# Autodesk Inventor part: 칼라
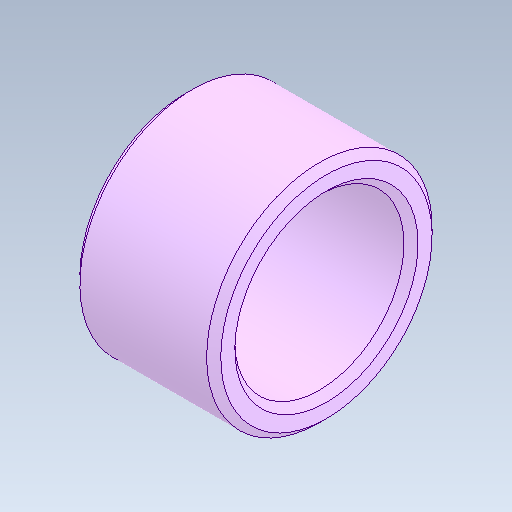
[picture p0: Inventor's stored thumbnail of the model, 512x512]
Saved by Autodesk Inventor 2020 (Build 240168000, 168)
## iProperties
Created: 2024-07
Part Number: 칼라
Material: 강철, 합금
Document SubType Name: Modeling
Designer: oem
Density: 7.73 g/cm^3
Appearance: 기본값
Author: jhkim
Sending System: Autodesk Inventor 2025
Preprocessor: ST-DEVELOPER v20
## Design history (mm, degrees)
feature "솔리드1"
node "솔리드2"
